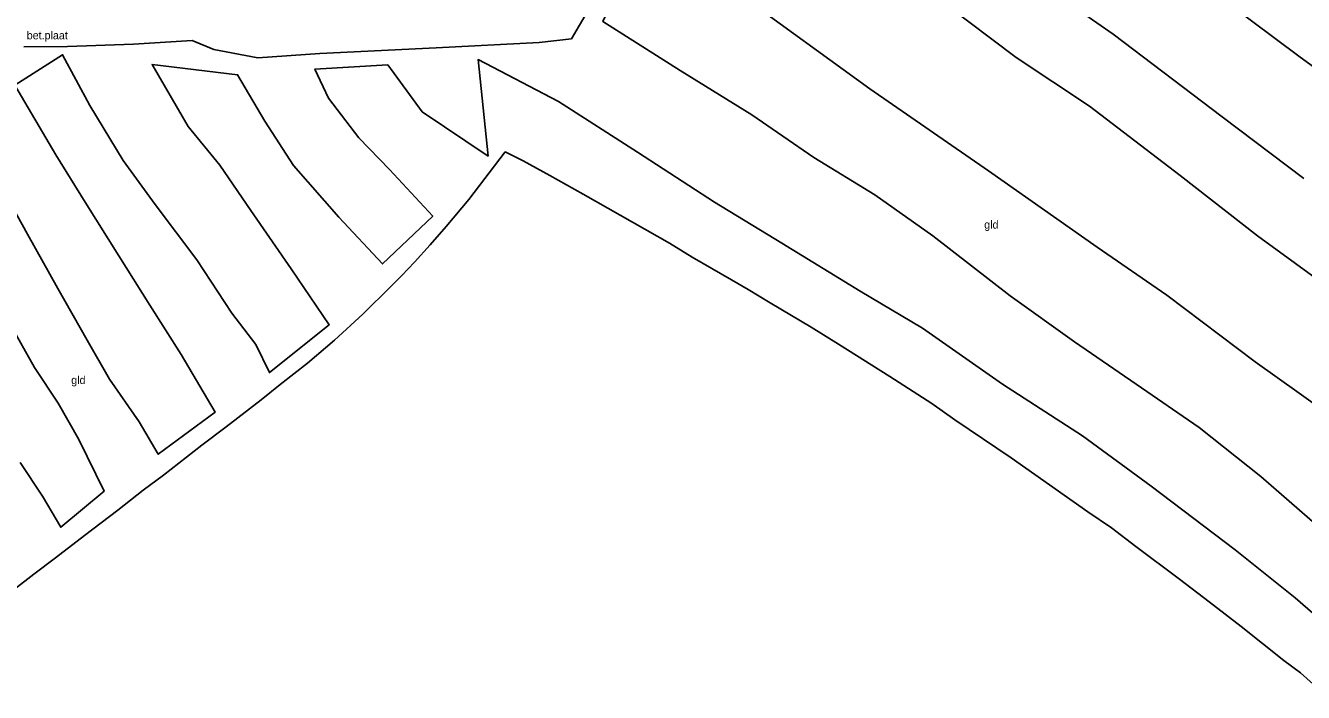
# Model space of a CAD drawing. Extents: x 154825 to 158680, y 370717 to 378075.
# Drawn here: x 155492.9 to 155652.5, y 377118.6 to 377201.9 of the extents above; entities that cross this region are included whole.
import ezdxf

# ---------------------------------------------------------------- set-up
doc = ezdxf.new("R2010")
doc.units = 0
for name, color, linetype in [('grasland_productiegrasl(vs)', 7, 'Continuous'), ('hoogteverschillijn', 7, 'Continuous'), ('maaiveldlijn algemeen - verharding algemeen', 7, 'Continuous'), ('tegelverh(vs)', 7, 'Continuous'), ('vlak_Grasland', 7, 'Continuous')]:
    doc.layers.add(name, color=color, linetype=linetype)

msp = doc.modelspace()

# ---------------------------------------------------------------- linework, layer by layer
at = {"layer": 'hoogteverschillijn'}
for points in [[(155664.84, 377188.62), (155651.94, 377198.03), (155640.27, 377206.76), (155629, 377215.41), (155617.68, 377223.48), (155606.64, 377231.62), (155595.33, 377239.35), (155584.37, 377243.59), (155574.16, 377248.47), (155583.75, 377250.36), (155586.04, 377254.07), (155593.73, 377249.65), (155603.2, 377244.54), (155610, 377240.97), (155622.61, 377232.98), (155631.33, 377227.46), (155640.41, 377221.66), (155649.44, 377215.82), (155662.95, 377206.22)], [(155656.28, 377168.7), (155646.77, 377175.61), (155637.11, 377183.15), (155625.78, 377191.78), (155616.65, 377197.88), (155607.66, 377204.61), (155598.96, 377210.55), (155590.72, 377216.47), (155574.45, 377227.67), (155573.54, 377238.36), (155584.03, 377231.98), (155594.63, 377223.98), (155605.25, 377216.79), (155618.56, 377207.91), (155628.74, 377200.78), (155642.36, 377190.48), (155652.55, 377182.75)], [(155654.29, 377139.41), (155647.2, 377145.56), (155639.49, 377151.7), (155631.62, 377157.08), (155623.9, 377162.37), (155615.86, 377168.13), (155606.24, 377175.62), (155598.96, 377180.73), (155591.37, 377185.37), (155583.6, 377190.73), (155574.65, 377196.24), (155564.98, 377202.37), (155570.48, 377214.15), (155582.15, 377205.72), (155598.36, 377193.97), (155613.17, 377183.7), (155626.75, 377174.19), (155635.45, 377168.22), (155646.49, 377159.86), (155657.77, 377151.84)], [(155488.87, 377183.43), (155493.12, 377175.82), (155496.93, 377169.02), (155500.57, 377162.58), (155503.38, 377157.72), (155507.09, 377152.4), (155509.45, 377148.34), (155516.56, 377153.59), (155512.34, 377160.79), (155508.4, 377166.95), (155504.54, 377173.12), (155500.33, 377179.82), (155496.66, 377185.7), (155491.56, 377194.43), (155497.5, 377198.21), (155500.91, 377191.87), (155505.08, 377184.99), (155509.08, 377179.51), (155514.26, 377172.63), (155518.66, 377165.97), (155521.64, 377162.04), (155523.34, 377158.54), (155530.82, 377164.5), (155526.08, 377171.47), (155521.04, 377178.76), (155517.16, 377184.41), (155513.21, 377189.27), (155508.69, 377197.01), (155519.36, 377195.71), (155522.77, 377189.91), (155526.34, 377184.38), (155532, 377177.95), (155537.47, 377172.09), (155543.75, 377178.05), (155538.36, 377183.89), (155534.51, 377187.85), (155530.73, 377192.78), (155529.02, 377196.42), (155538.13, 377196.94), (155542.43, 377191.09), (155550.66, 377185.57), (155549.41, 377197.61), (155559.47, 377192.37), (155569.34, 377186.04), (155578.93, 377179.8), (155587.36, 377174.69), (155597.14, 377168.71), (155604.94, 377164.07), (155614.93, 377157.07), (155624.92, 377150.66), (155633.5, 377144.37), (155644, 377136.41), (155651.5, 377130.43), (155657.47, 377125.21)], [(155654.91, 377118.61), (155652.15, 377121.07), (155650.07, 377122.61), (155644.73, 377126.84), (155640.72, 377129.93), (155637.03, 377132.76), (155631.58, 377136.82), (155628.53, 377139.15), (155625.57, 377141.16), (155616.02, 377147.9), (155608.95, 377152.64), (155606.1, 377154.67), (155600.85, 377158.03), (155594.45, 377162.1), (155591.04, 377164.22), (155585.91, 377167.26), (155583.16, 377168.91), (155581.07, 377170.12), (155576.16, 377172.96), (155573.34, 377174.68), (155562.56, 377180.79), (155558.39, 377183.13), (155555.04, 377184.98), (155552.8, 377186.09), (155548.27, 377180.16), (155545.42, 377176.76), (155543.44, 377174.49), (155541.49, 377172.31), (155539.89, 377170.66), (155538.55, 377169.31), (155535.01, 377165.83), (155531.48, 377162.6), (155528.09, 377159.73), (155524.68, 377157.03), (155522.33, 377155.13), (155517.95, 377151.75), (155514.92, 377149.48), (155510.1, 377145.73), (155507.59, 377143.85), (155504.41, 377141.35), (155500.25, 377138.2), (155496.64, 377135.43), (155493.93, 377133.38), (155489.44, 377129.9)], [(155492.23, 377147.32), (155494.98, 377143.1), (155497.28, 377139.22), (155502.69, 377143.72), (155499.55, 377150.19), (155496.97, 377154.72), (155493.98, 377159.17), (155490.97, 377164.59)]]:
    msp.add_lwpolyline(points, dxfattribs=at)
at = {"layer": 'maaiveldlijn algemeen - verharding algemeen'}
msp.add_lwpolyline([(155569.08, 377250.67), (155568.93, 377241.99), (155568.69, 377220.11), (155568.63, 377214.6), (155565.36, 377207.56), (155561.07, 377200.21), (155557.04, 377199.73), (155544.17, 377199.08), (155529.63, 377198.36), (155521.9, 377197.83), (155516.41, 377198.85), (155513.7, 377199.97), (155506.37, 377199.52), (155498.14, 377199.22), (155492.65, 377199.2)], dxfattribs=at)
at = {"layer": 'vlak_Grasland'}
for points in [[(155492.65, 377199.2), (155498.14, 377199.22), (155506.37, 377199.52), (155513.7, 377199.97), (155516.41, 377198.85), (155521.9, 377197.83), (155529.63, 377198.36), (155544.17, 377199.08), (155557.04, 377199.73), (155561.07, 377200.21), (155565.36, 377207.56)], [(155654.91, 377118.61), (155652.15, 377121.07), (155650.07, 377122.61), (155644.73, 377126.84), (155640.72, 377129.93), (155637.03, 377132.76), (155631.58, 377136.82), (155628.53, 377139.15), (155625.57, 377141.16), (155616.02, 377147.9), (155608.95, 377152.64), (155606.1, 377154.67), (155600.85, 377158.03), (155594.45, 377162.1), (155591.04, 377164.22), (155585.91, 377167.26), (155583.16, 377168.91), (155581.07, 377170.12), (155576.16, 377172.96), (155573.34, 377174.68), (155562.56, 377180.79), (155558.39, 377183.13), (155555.04, 377184.98), (155552.8, 377186.09), (155548.27, 377180.16), (155545.42, 377176.76), (155543.44, 377174.49), (155541.49, 377172.31), (155539.89, 377170.66), (155538.55, 377169.31), (155535.01, 377165.83), (155531.48, 377162.6), (155528.09, 377159.73), (155524.68, 377157.03), (155522.33, 377155.13), (155517.95, 377151.75), (155514.92, 377149.48), (155510.1, 377145.73), (155507.59, 377143.85), (155504.41, 377141.35), (155500.25, 377138.2), (155496.64, 377135.43), (155493.93, 377133.38), (155489.44, 377129.9)]]:
    msp.add_lwpolyline(points, dxfattribs=at)

# ---------------------------------------------------------------- texts
at = {"layer": 'grasland_productiegrasl(vs)'}
for p in [(155612.64, 377176.51), (155498.59, 377157.11)]:
    msp.add_text('gld', height=1, dxfattribs=at).set_placement(p)
at = {"layer": 'tegelverh(vs)'}
msp.add_text('bet.plaat', height=1, dxfattribs=at).set_placement((155493.03, 377200.14))

doc.saveas('drawing.dxf')
